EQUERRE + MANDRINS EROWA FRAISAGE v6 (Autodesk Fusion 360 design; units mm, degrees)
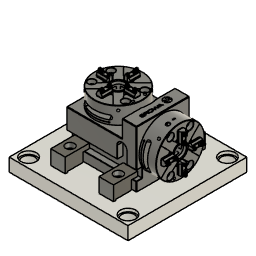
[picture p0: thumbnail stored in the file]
base_feature "Fonction de base1"
base_feature "Fonction de base1"
base_feature "Fonction de base1"
base_feature "Fonction de base1"
base_feature "Fonction de base1" bodies "Corps1"
as_built_joint "Réelle"
base_feature "Fonction de base1"
extrude "Extrusion" new body sketch "unnamed" distance 15
hole "Perçage1" HoleDiameter 11 CBDepth 10 CBDiameter 18 RefDim1 15 RefDim2 25
work_plane "Plan de construction1"
work_plane "Plan de construction2"
mirror "Symétrie miroir1" mirrorStitchTolerance 0.1
mirror "Symétrie miroir2" mirrorStitchTolerance 0.1
work_plane "Plan de construction1" AlongDistance 0
sketch "Esquisse" plane through (0, 0, 0) normal (0, 0, 1) x axis (1, 0, 0)
  circle C1 centre (-40.8271, 106.9755) radius 5.5
  circle C2 centre (59.1729, 106.9755) radius 5.5
  circle C3 centre (59.1729, -33.0245) radius 5.5
  circle C4 centre (-40.8271, -33.0245) radius 5.5
  point P2 (-40.8271, 106.9755)
  point P3 (-40.8271, 106.9755)
  point P4 (59.1729, 106.9755)
  point P5 (59.1729, 106.9755)
  point P6 (59.1729, -33.0245)
  point P7 (59.1729, -33.0245)
  point P8 (-40.8271, -33.0245)
  point P9 (-40.8271, -33.0245)
  coincident P2 P3
  coincident P4 P5
  coincident P6 P7
  coincident P8 P9
hole "Perçage1" HoleDiameter 8.526
offset_faces "DécalerLesFaces1" distance -1
offset_faces "DécalerLesFaces2" distance -1
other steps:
thread "Filetage" ThreadOffset 0 ThreadDepth 10
create_component "CreateComponent1"
create_component "CreateComponent2"
create_component "CreateComponent3"
create_component "CreateComponent1"
create_component "CreateComponent4"
named bodies: "Corps1"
